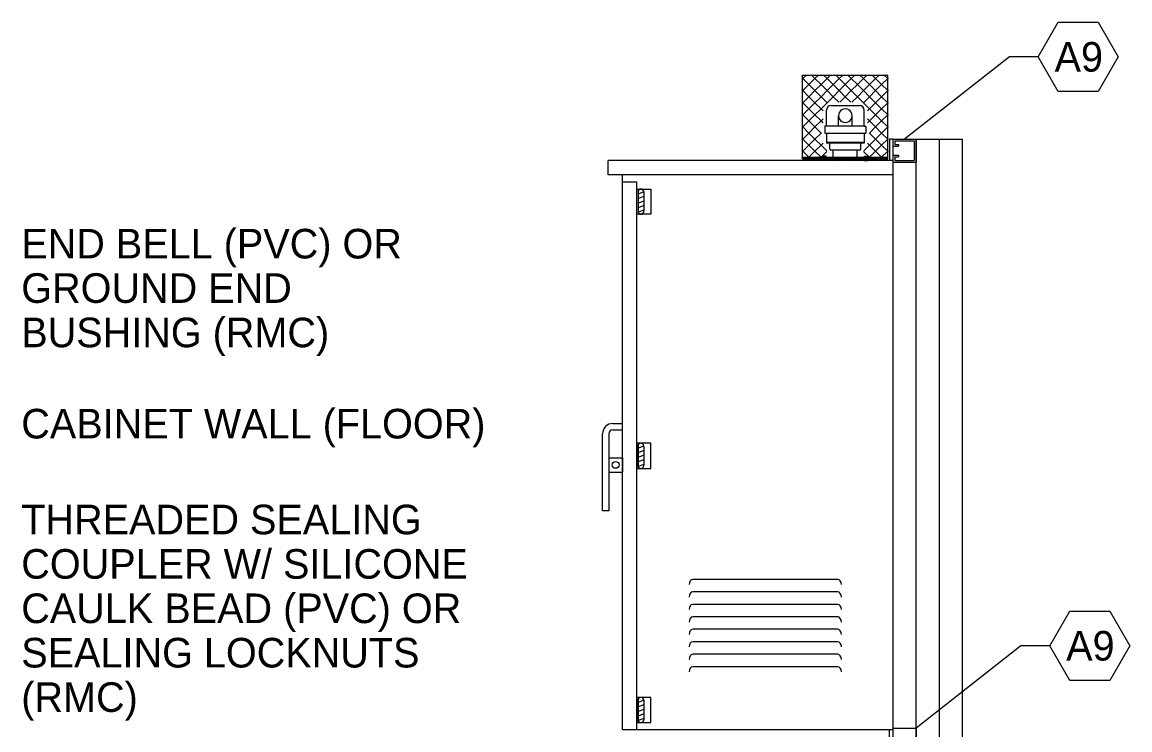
# Model space of a CAD drawing. Extents: x 99862 to 103151, y 100000 to 117076.
# Drawn here: x 100888 to 101487, y 103687 to 104070 of the extents above; entities that cross this region are included whole.
import ezdxf

# ---------------------------------------------------------------- set-up
doc = ezdxf.new("R2010")
doc.units = 0
for name, color, linetype in [('Level 1', 7, 'Continuous'), ('Level 11', 7, 'Continuous'), ('Level 15', 7, 'Continuous'), ('Level 20', 7, 'Continuous'), ('Level 40', 7, 'Continuous')]:
    doc.layers.add(name, color=color, linetype=linetype)

msp = doc.modelspace()

# ---------------------------------------------------------------- linework, layer by layer
at = {"layer": 'Level 1'}
for p, q in [((101309.78, 104040.92), (101355.95, 104040.92)), ((101309.78, 103996.48), (101309.78, 104040.92)), ((101309.95, 104039.04), (101311.84, 104040.92)), ((101316.5, 104039.04), (101314.61, 104040.92)), ((101318.39, 104040.92), (101316.5, 104039.04)), ((101321.16, 104040.92), (101323.05, 104039.04)), ((101323.05, 104039.04), (101324.93, 104040.92)), ((101327.71, 104040.92), (101329.59, 104039.04)), ((101329.59, 104039.04), (101331.48, 104040.92)), ((101334.25, 104040.92), (101336.14, 104039.04)), ((101336.14, 104039.04), (101338.03, 104040.92)), ((101340.8, 104040.92), (101342.69, 104039.04)), ((101342.69, 104039.04), (101344.57, 104040.92)), ((101347.35, 104040.92), (101349.23, 104039.04)), ((101351.12, 104040.92), (101349.23, 104039.04)), ((101355.78, 104039.04), (101353.89, 104040.92)), ((101355.95, 103996.48), (101355.95, 104040.92)), ((101309.78, 104039.21), (101309.95, 104039.04)), ((101309.95, 104039.04), (101309.78, 104038.87)), ((101313.23, 104035.76), (101309.95, 104039.04)), ((101309.95, 104032.49), (101313.23, 104035.76)), ((101316.5, 104039.04), (101313.23, 104035.76)), ((101313.23, 104035.76), (101316.5, 104032.49)), ((101319.77, 104035.76), (101316.5, 104039.04)), ((101316.5, 104032.49), (101319.77, 104035.76)), ((101323.05, 104039.04), (101319.77, 104035.76)), ((101319.77, 104035.76), (101323.05, 104032.49)), ((101326.32, 104035.76), (101323.05, 104039.04)), ((101323.05, 104032.49), (101326.32, 104035.76)), ((101329.59, 104039.04), (101326.32, 104035.76)), ((101326.32, 104035.76), (101329.59, 104032.49)), ((101332.87, 104035.76), (101329.59, 104039.04)), ((101329.59, 104032.49), (101332.87, 104035.76)), ((101336.14, 104039.04), (101332.87, 104035.76)), ((101332.87, 104035.76), (101336.14, 104032.49)), ((101339.41, 104035.76), (101336.14, 104039.04)), ((101336.14, 104032.49), (101339.41, 104035.76)), ((101342.69, 104039.04), (101339.41, 104035.76)), ((101339.41, 104035.76), (101342.69, 104032.49)), ((101345.96, 104035.76), (101342.69, 104039.04)), ((101342.69, 104032.49), (101345.96, 104035.76)), ((101349.23, 104039.04), (101345.96, 104035.76)), ((101345.96, 104035.76), (101349.23, 104032.49)), ((101349.23, 104039.04), (101352.51, 104035.76)), ((101352.51, 104035.76), (101349.23, 104032.49)), ((101352.51, 104035.76), (101355.78, 104039.04)), ((101355.78, 104032.49), (101352.51, 104035.76)), ((101355.95, 104039.21), (101355.78, 104039.04)), ((101355.78, 104039.04), (101355.95, 104038.87)), ((101309.78, 104032.66), (101309.95, 104032.49)), ((101309.95, 104032.49), (101309.78, 104032.32)), ((101313.23, 104029.22), (101309.95, 104032.49)), ((101309.95, 104025.94), (101313.23, 104029.22)), ((101316.5, 104032.49), (101313.23, 104029.22)), ((101313.23, 104029.22), (101316.5, 104025.94)), ((101319.77, 104029.22), (101316.5, 104032.49)), ((101316.5, 104025.94), (101319.77, 104029.22)), ((101323.05, 104032.49), (101319.77, 104029.22)), ((101319.77, 104029.22), (101323.05, 104025.94)), ((101326.32, 104029.22), (101323.05, 104032.49)), ((101323.05, 104025.94), (101326.32, 104029.22)), ((101329.59, 104032.49), (101326.32, 104029.22)), ((101326.32, 104029.22), (101329.3, 104026.23)), ((101332.87, 104029.22), (101329.59, 104032.49)), ((101329.89, 104026.23), (101332.87, 104029.22)), ((101336.14, 104032.49), (101332.87, 104029.22)), ((101332.87, 104029.22), (101335.85, 104026.23)), ((101339.41, 104029.22), (101336.14, 104032.49)), ((101336.43, 104026.23), (101339.41, 104029.22)), ((101342.69, 104032.49), (101339.41, 104029.22)), ((101339.41, 104029.22), (101342.69, 104025.94)), ((101345.96, 104029.22), (101342.69, 104032.49)), ((101342.69, 104025.94), (101345.96, 104029.22)), ((101349.23, 104032.49), (101345.96, 104029.22)), ((101345.96, 104029.22), (101349.23, 104025.94)), ((101349.23, 104032.49), (101352.51, 104029.22)), ((101352.51, 104029.22), (101349.23, 104025.94)), ((101352.51, 104029.22), (101355.78, 104032.49)), ((101355.78, 104025.94), (101352.51, 104029.22)), ((101355.95, 104032.66), (101355.78, 104032.49)), ((101355.78, 104032.49), (101355.95, 104032.32)), ((101309.78, 104026.11), (101309.95, 104025.94)), ((101309.95, 104025.94), (101309.78, 104025.77)), ((101313.23, 104022.67), (101309.95, 104025.94)), ((101309.95, 104019.4), (101313.23, 104022.67)), ((101316.5, 104025.94), (101313.23, 104022.67)), ((101313.23, 104022.67), (101316.5, 104019.4)), ((101319.77, 104022.67), (101316.5, 104025.94)), ((101316.5, 104019.4), (101319.77, 104022.67)), ((101323.05, 104025.94), (101319.77, 104022.67)), ((101319.77, 104022.67), (101320.83, 104021.61)), ((101322.68, 104013.27), (101322.68, 104021.91)), ((101323.21, 104025.78), (101323.05, 104025.94)), ((101325.15, 104024.38), (101340.58, 104024.38)), ((101342.69, 104025.94), (101342.52, 104025.78)), ((101345.96, 104022.67), (101342.69, 104025.94)), ((101343.05, 104013.27), (101343.05, 104021.91)), ((101344.9, 104021.61), (101345.96, 104022.67)), ((101349.23, 104025.94), (101345.96, 104022.67)), ((101345.96, 104022.67), (101349.23, 104019.4)), ((101349.23, 104025.94), (101352.51, 104022.67)), ((101352.51, 104022.67), (101349.23, 104019.4)), ((101352.51, 104022.67), (101355.78, 104025.94)), ((101355.78, 104019.4), (101352.51, 104022.67)), ((101355.95, 104026.11), (101355.78, 104025.94)), ((101355.78, 104025.94), (101355.95, 104025.77)), ((101309.78, 104019.56), (101309.95, 104019.4)), ((101309.95, 104019.4), (101309.78, 104019.23)), ((101313.23, 104016.12), (101309.95, 104019.4)), ((101309.95, 104012.85), (101313.23, 104016.12)), ((101316.5, 104019.4), (101313.23, 104016.12)), ((101313.23, 104016.12), (101316.5, 104012.85)), ((101319.77, 104016.12), (101316.5, 104019.4)), ((101316.5, 104012.85), (101319.77, 104016.12)), ((101320.83, 104017.18), (101319.77, 104016.12)), ((101319.77, 104016.12), (101320.77, 104015.12)), ((101329.16, 104013.27), (101329.16, 104018.95)), ((101336.57, 104013.27), (101336.57, 104018.95)), ((101345.96, 104016.12), (101344.9, 104017.18)), ((101344.96, 104015.12), (101345.96, 104016.12)), ((101349.23, 104019.4), (101345.96, 104016.12)), ((101345.96, 104016.12), (101349.23, 104012.85)), ((101349.23, 104019.4), (101352.51, 104016.12)), ((101352.51, 104016.12), (101349.23, 104012.85)), ((101352.51, 104016.12), (101355.78, 104019.4)), ((101355.78, 104012.85), (101352.51, 104016.12)), ((101355.95, 104019.57), (101355.78, 104019.4)), ((101355.78, 104019.4), (101355.95, 104019.23)), ((101309.78, 104013.02), (101309.95, 104012.85)), ((101309.95, 104012.85), (101309.78, 104012.68)), ((101313.23, 104009.57), (101309.95, 104012.85)), ((101309.95, 104006.3), (101313.23, 104009.57)), ((101316.5, 104012.85), (101313.23, 104009.57)), ((101313.23, 104009.57), (101316.5, 104006.3)), ((101319.77, 104009.57), (101316.5, 104012.85)), ((101316.5, 104006.3), (101319.77, 104009.57)), ((101319.9, 104009.71), (101319.77, 104009.57)), ((101319.77, 104009.57), (101319.9, 104009.44)), ((101322.68, 104013.27), (101321.76, 104013.27)), ((101321.76, 104013.27), (101321.76, 104009.57)), ((101321.76, 104009.57), (101343.98, 104009.57)), ((101343.05, 104013.27), (101322.68, 104013.27)), ((101322.68, 104009.57), (101322.68, 104004.01)), ((101343.05, 104013.27), (101343.98, 104013.27)), ((101343.05, 104009.57), (101343.05, 104004.01)), ((101343.98, 104013.27), (101343.98, 104009.57)), ((101345.96, 104009.57), (101345.83, 104009.71)), ((101345.83, 104009.44), (101345.96, 104009.57)), ((101349.23, 104012.85), (101345.96, 104009.57)), ((101345.96, 104009.57), (101349.23, 104006.3)), ((101349.23, 104012.85), (101352.51, 104009.57)), ((101352.51, 104009.57), (101349.23, 104006.3)), ((101352.51, 104009.57), (101355.78, 104012.85)), ((101355.78, 104006.3), (101352.51, 104009.57)), ((101355.95, 104013.02), (101355.78, 104012.85)), ((101355.78, 104012.85), (101355.95, 104012.68)), ((101309.78, 104006.47), (101309.95, 104006.3)), ((101309.95, 104006.3), (101309.78, 104006.13)), ((101313.23, 104003.03), (101309.95, 104006.3)), ((101316.5, 104006.3), (101313.23, 104003.03)), ((101319.77, 104003.03), (101316.5, 104006.3)), ((101320.83, 104004.09), (101319.77, 104003.03)), ((101343.05, 104004.48), (101322.68, 104004.48)), ((101343.05, 104004.01), (101322.68, 104004.01)), ((101324.53, 104000.77), (101324.53, 104004.01)), ((101341.2, 104000.77), (101341.2, 104004.01)), ((101345.96, 104003.03), (101344.9, 104004.08)), ((101349.23, 104006.3), (101345.96, 104003.03)), ((101349.23, 104006.3), (101352.51, 104003.03)), ((101352.51, 104003.03), (101355.78, 104006.3)), ((101355.95, 104006.47), (101355.78, 104006.3)), ((101355.78, 104006.3), (101355.95, 104006.13)), ((101309.78, 103999.92), (101309.95, 103999.75)), ((101309.95, 103999.75), (101309.78, 103999.58)), ((101309.95, 103999.75), (101313.23, 104003.03)), ((101313.23, 103996.48), (101309.95, 103999.75)), ((101313.23, 104003.03), (101316.5, 103999.75)), ((101316.5, 103999.75), (101313.23, 103996.48)), ((101316.5, 103999.75), (101319.77, 104003.03)), ((101319.77, 103996.48), (101316.5, 103999.75)), ((101319.77, 104003.03), (101322.82, 103999.98)), ((101322.96, 103999.67), (101319.77, 103996.48)), ((101340.74, 104000.31), (101325, 104000.31)), ((101326.39, 103996.61), (101326.39, 104000.31)), ((101339.35, 103996.61), (101339.35, 104000.31)), ((101345.96, 103996.48), (101342.77, 103999.67)), ((101342.91, 103999.98), (101345.96, 104003.03)), ((101345.96, 104003.03), (101349.23, 103999.75)), ((101349.23, 103999.75), (101345.96, 103996.48)), ((101352.51, 104003.03), (101349.23, 103999.75)), ((101349.23, 103999.75), (101352.51, 103996.48)), ((101355.78, 103999.75), (101352.51, 104003.03)), ((101352.51, 103996.48), (101355.78, 103999.75)), ((101355.95, 103999.92), (101355.78, 103999.75)), ((101355.78, 103999.75), (101355.95, 103999.58)), ((101309.78, 103996.48), (101355.95, 103996.48)), ((101309.78, 103995.68), (101309.78, 103996.4)), ((101309.78, 103996.4), (101355.95, 103996.4)), ((101309.78, 103995.68), (101355.95, 103995.68)), ((101337.5, 103994.75), (101328.24, 103994.75)), ((101355.95, 103995.68), (101355.95, 103996.4)), ((101220.14, 103965.63), (101220.14, 103979.31)), ((101220.9, 103977.77), (101220.9, 103967.17)), ((101223.98, 103977.77), (101220.9, 103976.58)), ((101223.98, 103975.3), (101220.9, 103974.11)), ((101223.98, 103977.77), (101223.98, 103967.17)), ((101223.98, 103972.82), (101220.9, 103971.63)), ((101223.98, 103970.35), (101220.9, 103969.16)), ((101223.98, 103967.87), (101220.98, 103966.71)), ((101207.26, 103852.57), (101212.44, 103852.57)), ((101207.26, 103849.16), (101212.44, 103849.16)), ((101201.68, 103805.39), (101201.68, 103846.99)), ((101205.09, 103846.99), (101205.09, 103805.39)), ((101220.14, 103841.92), (101220.14, 103828.25)), ((101220.9, 103840.38), (101220.9, 103829.78)), ((101223.98, 103840.38), (101220.9, 103839.19)), ((101223.98, 103837.91), (101220.9, 103836.72)), ((101223.98, 103840.38), (101223.98, 103829.78)), ((101205.09, 103834.03), (101212.44, 103834.03)), ((101212.44, 103834.03), (101212.44, 103826.33)), ((101223.98, 103835.43), (101220.9, 103834.25)), ((101223.98, 103832.96), (101220.9, 103831.77)), ((101223.98, 103830.48), (101220.98, 103829.32)), ((101205.09, 103826.33), (101212.44, 103826.33)), ((101205.09, 103805.39), (101201.68, 103805.39)), ((101220.14, 103704.53), (101220.14, 103690.86)), ((101220.9, 103702.99), (101220.9, 103692.4)), ((101223.98, 103702.99), (101220.9, 103701.81)), ((101223.98, 103700.52), (101220.9, 103699.33)), ((101223.98, 103702.99), (101223.98, 103692.4)), ((101223.98, 103698.04), (101220.9, 103696.86)), ((101223.98, 103695.57), (101220.9, 103694.38)), ((101223.98, 103693.1), (101220.98, 103691.94))]:
    msp.add_line(p, q, dxfattribs=at)
for points in [[(101220.14, 103979.31), (101227.83, 103979.31), (101227.83, 103965.63), (101220.14, 103965.63)], [(101220.14, 103828.25), (101227.83, 103828.25), (101227.83, 103841.92), (101220.14, 103841.92)], [(101220.14, 103690.86), (101227.83, 103690.86), (101227.83, 103704.53), (101220.14, 103704.53)]]:
    msp.add_lwpolyline(points, dxfattribs=at)
msp.add_circle((101208.77, 103830.18), 1.83, dxfattribs=at)
for centre, radius, start, end in [((101325.15, 104021.91), 2.47, 90, 180), ((101332.87, 104018.95), 3.7, 0, 180.00029), ((101340.58, 104021.91), 2.47, 0, 90), ((101332.87, 104018.95), 3.7, 179.99971, 360), ((101325, 104000.77), 0.463, 180, 270), ((101340.74, 104000.77), 0.463, 270, 0), ((101328.24, 103996.61), 1.85, 180, 270), ((101337.5, 103996.61), 1.85, 270, 0), ((101222.44, 103977.77), 1.54, 90, 180), ((101222.44, 103977.77), 1.54, 0, 90), ((101222.44, 103967.17), 1.54, 180, 270), ((101222.44, 103967.17), 1.54, 270, 0), ((101207.26, 103846.99), 5.58, 90, 180), ((101207.26, 103846.99), 2.17, 90, 180), ((101222.44, 103840.38), 1.54, 90, 180), ((101222.44, 103840.38), 1.54, 0, 90), ((101222.44, 103829.78), 1.54, 180, 270), ((101222.44, 103829.78), 1.54, 270, 0), ((101222.44, 103702.99), 1.54, 90, 180), ((101222.44, 103702.99), 1.54, 0, 90), ((101222.44, 103692.4), 1.54, 180, 270), ((101222.44, 103692.4), 1.54, 270, 0)]:
    msp.add_arc(centre, radius, start, end, dxfattribs=at)
at = {"layer": 'Level 11'}
for p, q in [((101328.78, 103768.27), (101250.43, 103768.27)), ((101328.78, 103761.53), (101250.43, 103761.53)), ((101328.78, 103754.78), (101250.43, 103754.78)), ((101328.78, 103748.04), (101250.43, 103748.04)), ((101328.78, 103741.29), (101250.43, 103741.29)), ((101328.78, 103734.55), (101250.43, 103734.55)), ((101328.78, 103727.81), (101250.43, 103727.81)), ((101328.78, 103721.06), (101250.43, 103721.06))]:
    msp.add_line(p, q, dxfattribs=at)
for centre, start_param, end_param in [((101250.43, 103765.47), 0, 1.570796), ((101328.78, 103765.47), 4.712389, 6.283185), ((101250.43, 103758.73), 0, 1.570796), ((101328.78, 103758.73), 4.712389, 6.283185), ((101250.43, 103751.98), 0, 1.570796), ((101328.78, 103751.98), 4.712389, 6.283185), ((101250.43, 103745.24), 0, 1.570796), ((101328.78, 103745.24), 4.712389, 6.283185), ((101250.43, 103738.5), 0, 1.570796), ((101328.78, 103738.5), 4.712389, 6.283185), ((101250.43, 103731.75), 0, 1.570796), ((101328.78, 103731.75), 4.712389, 6.283185), ((101250.43, 103725.01), 0, 1.570796), ((101328.78, 103725.01), 4.712389, 6.283185), ((101250.43, 103718.26), 0, 1.570796), ((101328.78, 103718.26), 4.712389, 6.283185)]:
    msp.add_ellipse(centre, major_axis=(0, 2.8), ratio=0.707107, start_param=start_param, end_param=end_param, dxfattribs=at)
at = {"layer": 'Level 15'}
for p, q in [((101421.53, 104050.76), (101364.9, 104006.3)), ((101437.12, 104050.76), (101421.53, 104050.76)), ((101358.65, 104006.3), (101356.72, 104006.3)), ((101356.72, 104006.3), (101356.72, 103994.75)), ((101358.65, 103987.06), (101204.75, 103987.06)), ((101212.44, 103983.21), (101220.14, 103983.21)), ((101220.14, 103686.95), (101220.14, 103983.21)), ((101427.78, 103732.39), (101371.15, 103687.93)), ((101443.37, 103732.39), (101427.78, 103732.39)), ((101356.72, 103675.41), (101356.72, 103686.95))]:
    msp.add_line(p, q, dxfattribs=at)
at = {"layer": 'Level 20'}
for points in [[(101437.12, 104050.76), (101447.94, 104069.51), (101469.59, 104069.51), (101480.4, 104050.76), (101469.59, 104032.01), (101447.94, 104032.01), (101437.12, 104050.76)], [(101443.37, 103732.39), (101454.2, 103751.14), (101475.85, 103751.14), (101486.65, 103732.39), (101475.85, 103713.65), (101454.2, 103713.65), (101443.37, 103732.39)]]:
    msp.add_lwpolyline(points, dxfattribs=at)
at = {"layer": 'Level 40'}
for p, q in [((101358.65, 104006.3), (101358.65, 103675.41)), ((101358.65, 104006.3), (101371.15, 104006.3)), ((101358.65, 104006.3), (101358.65, 104002.42)), ((101359.64, 104005.32), (101370.18, 104005.32)), ((101359.64, 104005.32), (101359.64, 104003.41)), ((101370.18, 104005.32), (101370.18, 103994.75)), ((101371.15, 104006.3), (101371.15, 103993.78)), ((101371.19, 103498.6), (101371.19, 104006.3)), ((101371.19, 104006.3), (101396.21, 104006.3)), ((101383.7, 103498.6), (101383.7, 104006.3)), ((101396.21, 103498.6), (101396.21, 104006.3)), ((101358.65, 104002.47), (101361.61, 104002.47)), ((101359.64, 104003.41), (101361.61, 104003.41)), ((101361.61, 104003.41), (101361.61, 104002.47)), ((101358.65, 103994.75), (101204.75, 103994.75)), ((101204.75, 103987.06), (101204.75, 103994.75)), ((101358.65, 103997.58), (101361.61, 103997.58)), ((101358.65, 103997.58), (101358.65, 103993.78)), ((101358.65, 103993.78), (101371.15, 103993.78)), ((101359.64, 103996.65), (101361.61, 103996.65)), ((101359.64, 103996.65), (101359.64, 103994.75)), ((101359.64, 103994.75), (101370.18, 103994.75)), ((101361.61, 103997.58), (101361.61, 103996.65)), ((101212.44, 103686.95), (101212.44, 103987.06)), ((101358.65, 103686.95), (101212.44, 103686.95)), ((101358.65, 103687.93), (101371.15, 103687.93)), ((101358.65, 103687.93), (101358.65, 103684.05)), ((101371.15, 103687.93), (101371.15, 103675.41))]:
    msp.add_line(p, q, dxfattribs=at)
for points in [[(101322.79, 103994.94), (101322.79, 103994.75), (101320.72, 103994.75), (101320.72, 103994.94)], [(101322.77, 103995.07), (101322.77, 103994.94), (101320.75, 103994.94), (101320.75, 103995.07)], [(101322.51, 103996.42), (101322.51, 103997.02), (101321, 103997.02), (101321, 103996.42)], [(101322.51, 103995.07), (101322.51, 103995.68), (101321, 103995.68), (101321, 103995.07)], [(101342.94, 103994.94), (101342.94, 103994.75), (101345.01, 103994.75), (101345.01, 103994.94)], [(101342.97, 103995.07), (101342.97, 103994.94), (101344.99, 103994.94), (101344.99, 103995.07)], [(101343.22, 103996.42), (101343.22, 103997.02), (101344.74, 103997.02), (101344.74, 103996.42)], [(101343.22, 103995.07), (101343.22, 103995.68), (101344.74, 103995.68), (101344.74, 103995.07)]]:
    msp.add_lwpolyline(points, close=True, dxfattribs=at)

# ---------------------------------------------------------------- texts
at = {"layer": 'Level 20'}
for s, p in [('A9', (101445.98, 104042.76)), ('END BELL (PVC) OR', (100887.56, 103941.77)), ('GROUND END', (100887.56, 103917.77)), ('BUSHING (RMC)', (100887.56, 103893.77)), ('CABINET WALL (FLOOR)', (100887.56, 103844.47)), ('THREADED SEALING', (100887.56, 103792.66)), ('COUPLER W/ SILICONE', (100887.56, 103768.66)), ('CAULK BEAD (PVC) OR', (100887.56, 103744.66)), ('A9', (101452.23, 103724.4)), ('SEALING LOCKNUTS', (100887.56, 103720.66)), ('(RMC)', (100887.56, 103696.66))]:
    msp.add_text(s, height=16, dxfattribs=at).set_placement(p)

doc.saveas('drawing.dxf')
